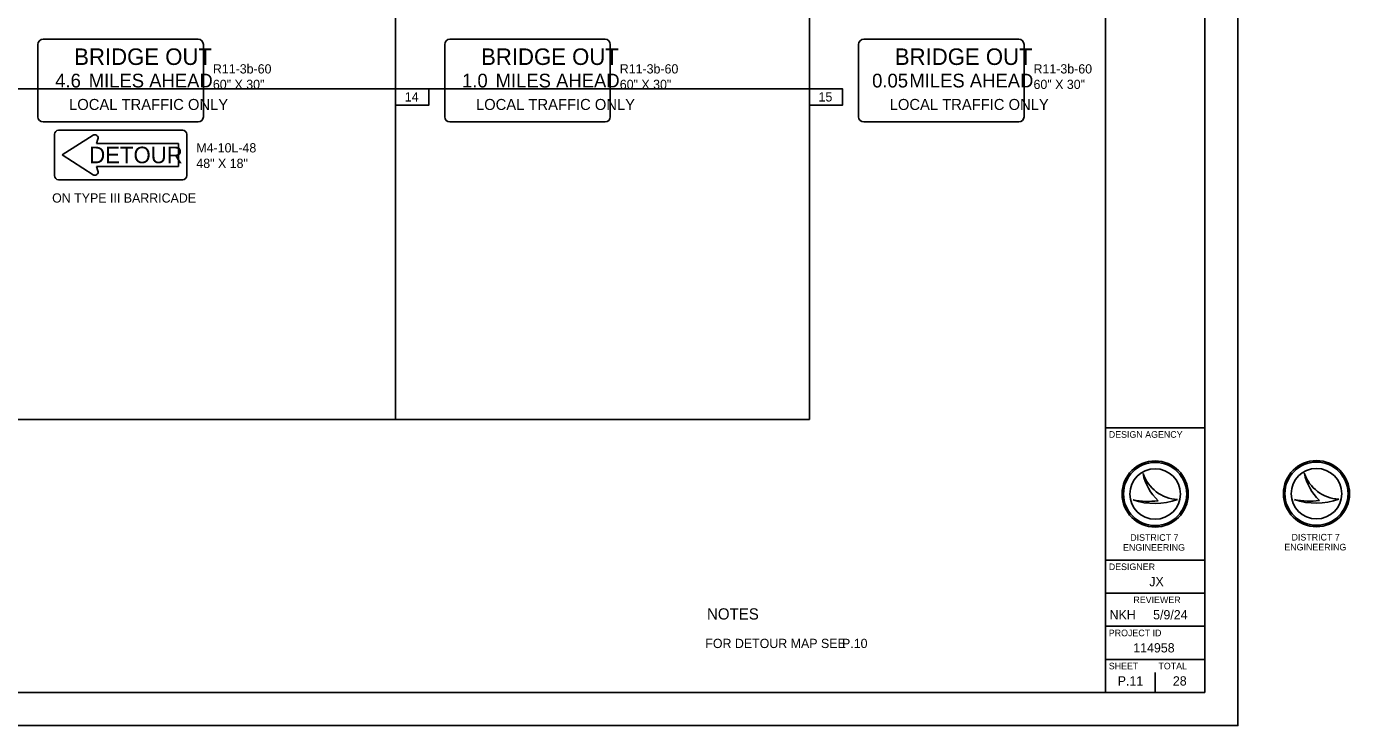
# Model space of a CAD drawing. Extents: x 0 to 714, y 0 to 440.
# Drawn here: x 314 to 713.7, y 0 to 211.4 of the extents above; entities that cross this region are included whole.
import ezdxf

# ---------------------------------------------------------------- set-up
doc = ezdxf.new("R2010")
doc.units = 0
for name, color, linetype in [('SC_Scratch1', 7, 'Continuous'), ('SH_Border', 7, 'Continuous'), ('SH_Cut_Line', 7, 'Continuous'), ('SH_Data', 7, 'Continuous'), ('SH_Text', 7, 'Continuous'), ('SN_P_Signs', 7, 'Continuous'), ('SN_P_Text', 7, 'Continuous')]:
    doc.layers.add(name, color=color, linetype=linetype)

msp = doc.modelspace()

# ---------------------------------------------------------------- linework, layer by layer
at = {"layer": 'SC_Scratch1'}
for p, q in [((425.54, 292.53), (425.54, 192.53)), ((550.54, 292.53), (550.54, 192.53)), ((50.54, 192.53), (350.54, 192.53)), ((350.54, 192.53), (500.54, 192.53)), ((375.54, 192.53), (550.54, 192.53)), ((425.54, 192.53), (425.54, 92.53)), ((550.54, 192.53), (550.54, 92.53)), ((225.54, 92.53), (375.54, 92.53)), ((375.54, 92.53), (550.54, 92.53))]:
    msp.add_line(p, q, dxfattribs=at)
at = {"layer": 'SH_Border'}
for p, q in [((640, 10), (640, 430)), ((640, 90), (670, 90)), ((640, 50), (670, 50)), ((640, 40), (670, 40)), ((640, 30), (670, 30)), ((640, 20), (670, 20))]:
    msp.add_line(p, q, dxfattribs=at)
msp.add_lwpolyline([(30, 430), (670, 430), (670, 10), (30, 10)], close=True, dxfattribs=at)
at = {"layer": 'SH_Cut_Line'}
msp.add_lwpolyline([(0, 0), (680, 0), (680, 440), (0, 440)], close=True, dxfattribs=at)
at = {"layer": 'SH_Data'}
for p, q in [((651.35, 76.19), (651.35, 76.19)), ((700.08, 76.29), (700.09, 76.29)), ((648.34, 68.19), (648.34, 68.19)), ((655, 70), (655, 70)), ((661.75, 68.37), (661.75, 68.37)), ((697.08, 68.29), (697.08, 68.29)), ((710.48, 68.47), (710.48, 68.47)), ((655, 10), (655, 16)), ((647.5, 13.5), (647.5, 13.5))]:
    msp.add_line(p, q, dxfattribs=at)
for centre, radius in [((655, 70), 10), ((703.74, 70.1), 10), ((655, 70), 9.54), ((655, 70), 9.54), ((655, 70), 7.64), ((703.74, 70.1), 9.54), ((703.74, 70.1), 9.54), ((703.74, 70.1), 7.64)]:
    msp.add_circle(centre, radius, dxfattribs=at)
for centre, radius, start, end in [((662.32, 79.95), 11.6, 198.9257, 198.9319), ((666.93, 79.4), 15.91, 191.6379, 191.6421), ((662.32, 79.95), 11.6, 198.9319, 267.1657), ((666.93, 79.4), 15.91, 191.6421, 226.0947), ((711.05, 80.05), 11.6, 198.9257, 198.9319), ((715.67, 79.5), 15.91, 191.6379, 191.6421), ((711.05, 80.05), 11.6, 198.9319, 267.1657), ((715.67, 79.5), 15.91, 191.6421, 226.0947), ((654.79, 87.4), 20.26, 251.4576, 290.0832), ((652.96, 93.09), 25.32, 259.4964, 259.4995), ((654.79, 87.4), 20.26, 251.4527, 251.4576), ((652.96, 93.09), 25.32, 259.4995, 276.6672), ((703.52, 87.5), 20.26, 251.4576, 290.0832), ((701.7, 93.18), 25.32, 259.4964, 259.4995), ((703.52, 87.5), 20.26, 251.4527, 251.4576), ((701.7, 93.18), 25.32, 259.4995, 276.6672)]:
    msp.add_arc(centre, radius, start, end, dxfattribs=at)
at = {"layer": 'SH_Text'}
for points in [[(425.54, 192.53), (435.54, 192.53), (435.54, 187.53), (425.54, 187.53)], [(550.54, 192.53), (560.54, 192.53), (560.54, 187.53), (550.54, 187.53)]]:
    msp.add_lwpolyline(points, close=True, dxfattribs=at)
at = {"layer": 'SN_P_Signs'}
for p, q in [((324.75, 172.49), (334.12, 178.46)), ((335.61, 177.31), (335.17, 175.93)), ((335.17, 175.93), (359.96, 175.93)), ((359.96, 175.93), (359.96, 169.05)), ((334.12, 166.51), (324.75, 172.49)), ((359.96, 169.05), (335.17, 169.05)), ((335.17, 169.05), (335.61, 167.66))]:
    msp.add_line(p, q, dxfattribs=at)
for points in [[(317.46, 205.93), (317.46, 184.05)], [(365.9, 207.49), (319.02, 207.49)], [(367.46, 184.05), (367.46, 205.93)], [(440.39, 205.93), (440.39, 184.05)], [(488.83, 207.49), (441.95, 207.49)], [(490.39, 184.05), (490.39, 205.93)], [(565.39, 205.93), (565.39, 184.05)], [(613.83, 207.49), (566.95, 207.49)], [(615.39, 184.05), (615.39, 205.93)], [(319.02, 182.49), (365.9, 182.49)], [(361.21, 179.99), (323.71, 179.99)], [(441.95, 182.49), (488.83, 182.49)], [(566.95, 182.49), (613.83, 182.49)], [(322.46, 178.74), (322.46, 166.24)], [(362.46, 166.24), (362.46, 178.74)], [(323.71, 164.99), (361.21, 164.99)]]:
    msp.add_lwpolyline(points, dxfattribs=at)
for centre, radius, start, end in [((319.02, 205.93), 1.56, 90, 180), ((365.9, 205.93), 1.56, 0, 90), ((441.95, 205.93), 1.56, 90, 180), ((488.83, 205.93), 1.56, 0, 90), ((566.95, 205.93), 1.56, 90, 180), ((613.83, 205.93), 1.56, 0, 90), ((319.02, 184.05), 1.56, 180, 270), ((365.9, 184.05), 1.56, 270, 0), ((441.95, 184.05), 1.56, 180, 270), ((488.83, 184.05), 1.56, 270, 0), ((566.95, 184.05), 1.56, 180, 270), ((613.83, 184.05), 1.56, 270, 0), ((323.71, 178.74), 1.25, 90, 180), ((361.21, 178.74), 1.25, 0, 90), ((334.66, 177.62), 1, 342.1811, 122.5109), ((323.71, 166.24), 1.25, 180, 270), ((334.66, 167.36), 1, 237.4891, 17.8189), ((361.21, 166.24), 1.25, 270, 0)]:
    msp.add_arc(centre, radius, start, end, dxfattribs=at)

# ---------------------------------------------------------------- texts
at = {"layer": 'SH_Data'}
for s, height, p in [('DESIGN AGENCY', 2, (641, 87)), ('DESIGNER', 2, (641, 47)), ('JX', 2.8, (653.23, 42.1)), ('REVIEWER', 2, (648.44, 37)), ('NKH', 2.8, (641.24, 32.1)), ('5/9/24', 2.8, (654.39, 32.1)), ('PROJECT ID', 2, (641, 27)), ('114958', 2.8, (648.39, 22.1)), ('SHEET', 2, (641, 17)), ('TOTAL', 2, (656, 17)), ('P.11', 2.8, (643.69, 12.1)), ('28', 2.8, (660.36, 12.1))]:
    msp.add_text(s, height=height, dxfattribs=at).set_placement(p)
at = {"layer": 'SH_Text'}
for s, height, p in [('14', 2.8, (428.31, 188.66)), ('15', 2.8, (553.31, 188.66)), ('DISTRICT 7', 2, (647.48, 55.85)), ('DISTRICT 7', 2, (696.22, 55.94)), ('ENGINEERING', 2, (645.3, 52.85)), ('ENGINEERING', 2, (694.04, 52.94)), ('NOTES', 3.4, (519.61, 32.05)), ('FOR DETOUR MAP SEE', 2.8, (519.1, 23.43)), ('P.10', 2.8, (560.4, 23.43))]:
    msp.add_text(s, height=height, dxfattribs=at).set_placement(p)
at = {"layer": 'SN_P_Signs'}
for s, height, p in [('BRIDGE OUT', 5, (328.43, 199.71)), ('BRIDGE OUT', 5, (451.36, 199.71)), ('BRIDGE OUT', 5, (576.36, 199.71)), ('4.6', 4.167, (322.69, 192.9)), ('MILES AHEAD', 4.1667, (332.81, 192.9)), ('1.0', 4.167, (445.61, 192.9)), ('MILES AHEAD', 4.1667, (455.74, 192.9)), ('0.05', 4.167, (569.5, 192.9)), ('MILES AHEAD', 4.1667, (580.74, 192.9)), ('LOCAL TRAFFIC ONLY', 3.3333, (326.88, 186.1)), ('LOCAL TRAFFIC ONLY', 3.3333, (449.81, 186.1)), ('LOCAL TRAFFIC ONLY', 3.3333, (574.81, 186.1)), ('DETOUR', 5, (332.97, 170))]:
    msp.add_text(s, height=height, dxfattribs=at).set_placement(p)
at = {"layer": 'SN_P_Text'}
for s, p in [('R11-3b-60', (370.33, 197.13)), ('R11-3b-60', (493.26, 197.13)), ('R11-3b-60', (618.26, 197.13)), ('60" X 30"', (370.33, 192.44)), ('60" X 30"', (493.26, 192.44)), ('60" X 30"', (618.26, 192.44)), ('M4-10L-48', (365.33, 173.26)), ('48" X 18"', (365.33, 168.57)), ('ON TYPE III BARRICADE', (321.76, 158.1))]:
    msp.add_text(s, height=2.8, dxfattribs=at).set_placement(p)

doc.saveas('drawing.dxf')
